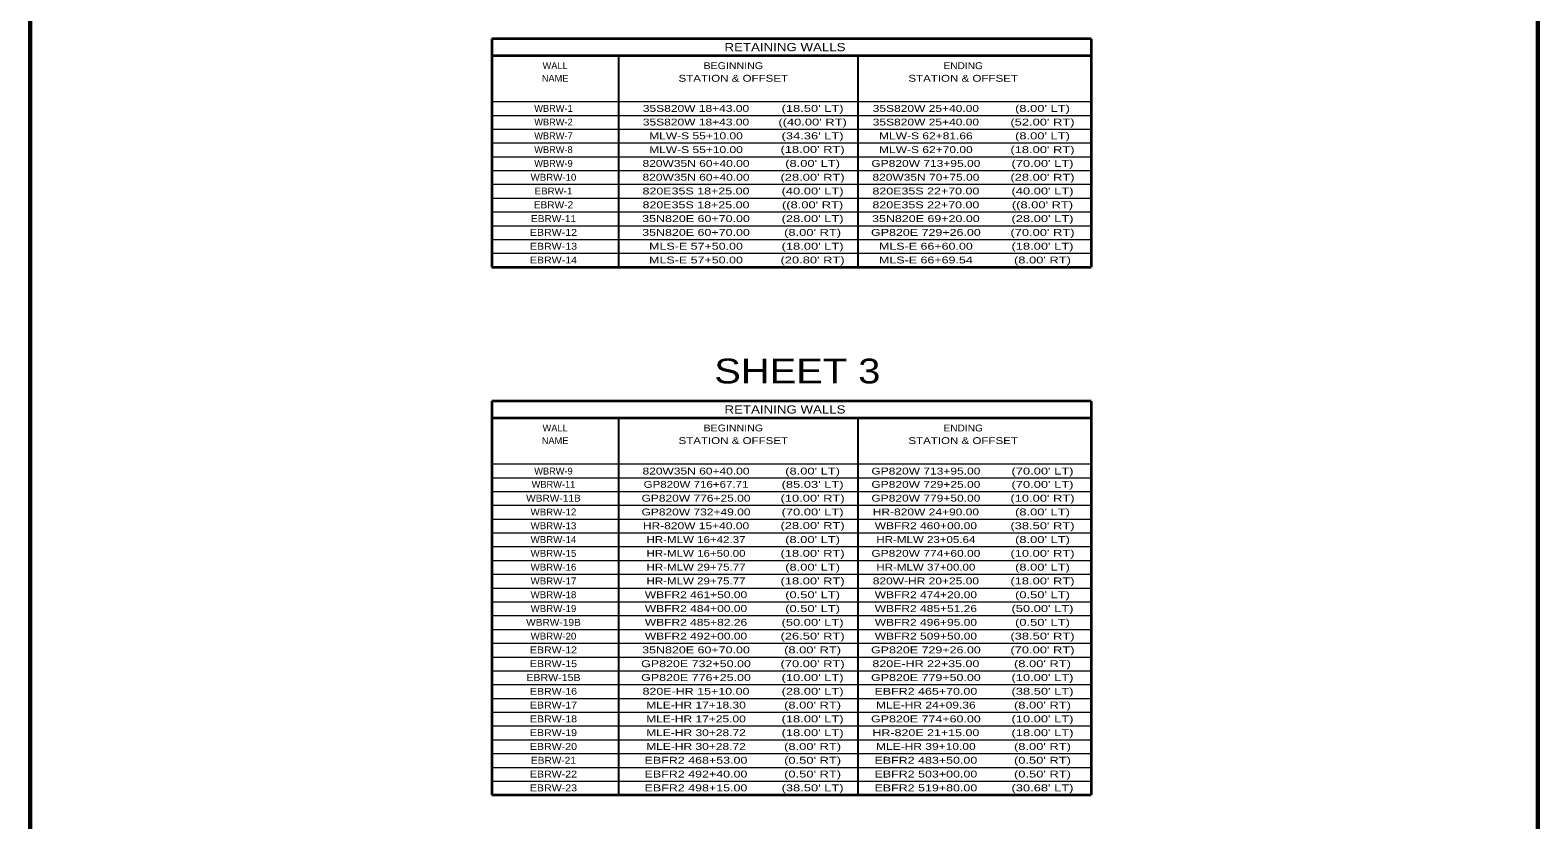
# Model space of a CAD drawing. Extents: x 2319482 to 2362028, y 6981189 to 6994467.
# Drawn here: x 2319482 to 2322105, y 6983285 to 6984659 of the extents above; entities that cross this region are included whole.
import ezdxf
from ezdxf.enums import TextEntityAlignment as Align

# ---------------------------------------------------------------- set-up
doc = ezdxf.new("R2010")
doc.units = 0
doc.header["$LTSCALE"] = 4.8
for name, color, linetype, lineweight in [('26', 7, 'Continuous', 13), ('45', 7, 'Continuous', 35), ('63', 7, 'Continuous', 60)]:
    doc.layers.add(name, color=color, linetype=linetype, lineweight=lineweight)

msp = doc.modelspace()

# ---------------------------------------------------------------- linework, layer by layer
at = {"layer": '26', "lineweight": 35}
for p, q in [((2321327.828, 6984643.503), (2320285.241, 6984643.503)), ((2320285.241, 6984643.503), (2320285.241, 6984246.37)), ((2321327.828, 6984643.503), (2321327.828, 6984246.37)), ((2320285.241, 6984614.703), (2321327.828, 6984614.703)), ((2320285.241, 6984246.37), (2321327.828, 6984246.37)), ((2321327.828, 6984013.126), (2320285.241, 6984013.126)), ((2320285.241, 6984013.126), (2320285.241, 6983327.993)), ((2321327.828, 6984013.126), (2321327.828, 6983327.993)), ((2320285.241, 6983984.326), (2321327.828, 6983984.326)), ((2320285.241, 6983327.993), (2321327.828, 6983327.993))]:
    msp.add_line(p, q, dxfattribs=at)
at = {"layer": '26', "lineweight": 25}
for p, q in [((2320505.241, 6984614.703), (2320505.241, 6984246.37)), ((2320921.935, 6984614.703), (2320921.935, 6984246.37)), ((2320505.241, 6983984.326), (2320505.241, 6983327.993)), ((2320921.935, 6983984.326), (2320921.935, 6983327.993))]:
    msp.add_line(p, q, dxfattribs=at)
at = {"layer": '26'}
for p, q in [((2320285.241, 6984534.37), (2321327.828, 6984534.37)), ((2320285.241, 6984510.37), (2321327.828, 6984510.37)), ((2320285.241, 6984486.37), (2321327.828, 6984486.37)), ((2320285.241, 6984462.37), (2321327.828, 6984462.37)), ((2320285.241, 6984438.37), (2321327.828, 6984438.37)), ((2320285.241, 6984414.37), (2321327.828, 6984414.37)), ((2320285.241, 6984390.37), (2321327.828, 6984390.37)), ((2320285.241, 6984366.37), (2321327.828, 6984366.37)), ((2320285.241, 6984342.37), (2321327.828, 6984342.37)), ((2320285.241, 6984318.37), (2321327.828, 6984318.37)), ((2320285.241, 6984294.37), (2321327.828, 6984294.37)), ((2320285.241, 6984270.37), (2321327.828, 6984270.37)), ((2320285.241, 6983903.993), (2321327.828, 6983903.993)), ((2320285.241, 6983879.993), (2321327.828, 6983879.993)), ((2320285.241, 6983855.993), (2321327.828, 6983855.993)), ((2320285.241, 6983831.993), (2321327.828, 6983831.993)), ((2320285.241, 6983807.993), (2321327.828, 6983807.993)), ((2320285.241, 6983783.993), (2321327.828, 6983783.993)), ((2320285.241, 6983759.993), (2321327.828, 6983759.993)), ((2320285.241, 6983735.993), (2321327.828, 6983735.993)), ((2320285.241, 6983711.993), (2321327.828, 6983711.993)), ((2320285.241, 6983687.993), (2321327.828, 6983687.993)), ((2320285.241, 6983663.993), (2321327.828, 6983663.993)), ((2320285.241, 6983639.993), (2321327.828, 6983639.993)), ((2320285.241, 6983615.993), (2321327.828, 6983615.993)), ((2320285.241, 6983591.993), (2321327.828, 6983591.993)), ((2320285.241, 6983567.993), (2321327.828, 6983567.993)), ((2320285.241, 6983543.993), (2321327.828, 6983543.993)), ((2320285.241, 6983519.993), (2321327.828, 6983519.993)), ((2320285.241, 6983495.993), (2321327.828, 6983495.993)), ((2320285.241, 6983471.993), (2321327.828, 6983471.993)), ((2320285.241, 6983447.993), (2321327.828, 6983447.993)), ((2320285.241, 6983423.993), (2321327.828, 6983423.993)), ((2320285.241, 6983399.993), (2321327.828, 6983399.993)), ((2320285.241, 6983375.993), (2321327.828, 6983375.993)), ((2320285.241, 6983351.993), (2321327.828, 6983351.993))]:
    msp.add_line(p, q, dxfattribs=at)
at = {"layer": '63'}
msp.add_lwpolyline([(2319481.784, 6985687.71), (2322105.179, 6985687.71), (2322105.179, 6981188.674), (2319481.784, 6981188.674)], close=True, dxfattribs=at)

# ---------------------------------------------------------------- texts
at = {"layer": '26'}
for s, height, width, p in [('RETAINING WALLS', 14.4, 1.2, (2320795.236, 6984621.904)), ('STATION & OFFSET', 12, 1.25, (2320705.236, 6984568.828)), ('BEGINNING', 12, 1.15, (2320705.237, 6984590.829)), ('STATION & OFFSET', 12, 1.25, (2321105.236, 6984568.829)), ('ENDING', 12, 1.1, (2321105.237, 6984590.827)), ('35S820W 18+43.00', 12, 1.3, (2320640.375, 6984516.425)), ("(18.50' LT)", 12, 1.4, (2320843.216, 6984516.424)), ('35S820W 25+40.00', 12, 1.3, (2321040.375, 6984516.425)), ("(8.00' LT)", 12, 1.4, (2321243.217, 6984516.424)), ('35S820W 18+43.00', 12, 1.3, (2320640.375, 6984492.724)), ("((40.00' RT)", 12, 1.4, (2320843.216, 6984492.723)), ('35S820W 25+40.00', 12, 1.3, (2321040.375, 6984492.724)), ("(52.00' RT)", 12, 1.4, (2321243.216, 6984492.723)), ('MLW-S 55+10.00', 12, 1.3, (2320640.374, 6984468.724)), ("(34.36' LT)", 12, 1.4, (2320843.216, 6984468.723)), ('MLW-S 62+81.66', 12, 1.3, (2321040.374, 6984468.724)), ("(8.00' LT)", 12, 1.4, (2321243.217, 6984468.723)), ('MLW-S 55+10.00', 12, 1.3, (2320640.374, 6984444.724)), ("(18.00' RT)", 12, 1.4, (2320843.216, 6984445.089)), ('MLW-S 62+70.00', 12, 1.3, (2321040.374, 6984444.724)), ("(18.00' RT)", 12, 1.4, (2321243.216, 6984444.723)), ('820W35N 60+40.00', 12, 1.3, (2320640.375, 6984420.724)), ("(8.00' LT)", 12, 1.4, (2320843.217, 6984420.723)), ('GP820W 713+95.00', 12, 1.3, (2321040.375, 6984420.724)), ("(70.00' LT)", 12, 1.4, (2321243.216, 6984420.723)), ('WBRW-10', 12, 1.05, (2320392.351, 6984396.724)), ('820W35N 60+40.00', 12, 1.3, (2320640.375, 6984396.724)), ("(28.00' RT)", 12, 1.4, (2320843.216, 6984396.723)), ('820W35N 70+75.00', 12, 1.3, (2321040.375, 6984396.724)), ("(28.00' RT)", 12, 1.4, (2321243.216, 6984396.723)), ('EBRW-1', 12, 1.05, (2320392.351, 6984372.724)), ('820E35S 18+25.00', 12, 1.35, (2320640.375, 6984372.724)), ("(40.00' LT)", 12, 1.4, (2320843.216, 6984372.723)), ('820E35S 22+70.00', 12, 1.35, (2321040.375, 6984372.724)), ("(40.00' LT)", 12, 1.4, (2321243.216, 6984372.723)), ('EBRW-2', 12, 1.1, (2320392.35, 6984348.724)), ('820E35S 18+25.00', 12, 1.35, (2320640.375, 6984348.724)), ("((8.00' RT)", 12, 1.4, (2320843.216, 6984348.723)), ('820E35S 22+70.00', 12, 1.35, (2321040.375, 6984348.724)), ("((8.00' RT)", 12, 1.4, (2321243.216, 6984348.723)), ('EBRW-11', 12, 1.1, (2320392.35, 6984324.724)), ('35N820E 60+70.00', 12, 1.35, (2320640.375, 6984324.724)), ("(28.00' LT)", 12, 1.4, (2320843.216, 6984324.723)), ('35N820E 69+20.00', 12, 1.35, (2321040.375, 6984324.724)), ("(28.00' LT)", 12, 1.4, (2321243.216, 6984324.723)), ('EBRW-12', 12, 1.15, (2320392.351, 6984300.724)), ('35N820E 60+70.00', 12, 1.35, (2320640.375, 6984300.724)), ("(8.00' RT)", 12, 1.4, (2320843.217, 6984300.723)), ('GP820E 729+26.00', 12, 1.35, (2321040.375, 6984300.724)), ("(70.00' RT)", 12, 1.4, (2321243.216, 6984300.723)), ('EBRW-13', 12, 1.15, (2320392.351, 6984276.724)), ('EBRW-14', 12, 1.15, (2320392.351, 6984252.724)), ('MLS-E 57+50.00', 12, 1.35, (2320640.374, 6984276.724)), ('MLS-E 57+50.00', 12, 1.35, (2320640.374, 6984252.724)), ("(20.80' RT)", 12, 1.4, (2320843.216, 6984252.723)), ("(18.00' LT)", 12, 1.4, (2320843.216, 6984276.723)), ('MLS-E 66+60.00', 12, 1.35, (2321040.374, 6984276.724)), ('MLS-E 66+69.54', 12, 1.35, (2321040.374, 6984252.724)), ("(18.00' LT)", 12, 1.4, (2321243.216, 6984276.723)), ("(8.00' RT)", 12, 1.4, (2321243.217, 6984252.723)), ('SHEET 3', 43.2, 1.2, (2320816.684, 6984043.936)), ('RETAINING WALLS', 14.4, 1.2, (2320795.236, 6983991.527)), ('STATION & OFFSET', 12, 1.25, (2320705.236, 6983938.451)), ('BEGINNING', 12, 1.15, (2320705.237, 6983960.452)), ('STATION & OFFSET', 12, 1.25, (2321105.236, 6983938.452)), ('ENDING', 12, 1.1, (2321105.237, 6983960.45)), ('820W35N 60+40.00', 12, 1.3, (2320640.375, 6983885.466)), ("(8.00' LT)", 12, 1.4, (2320843.217, 6983885.465)), ('GP820W 713+95.00', 12, 1.3, (2321040.375, 6983885.466)), ("(70.00' LT)", 12, 1.4, (2321243.216, 6983885.465)), ('GP820W 716+67.71', 12, 1.25, (2320640.374, 6983862.347)), ("(85.03' LT)", 12, 1.4, (2320843.216, 6983862.346)), ('GP820W 729+25.00', 12, 1.3, (2321040.375, 6983862.347)), ("(70.00' LT)", 12, 1.4, (2321243.216, 6983862.346)), ('WBRW-11B', 12, 1.1, (2320392.35, 6983838.347)), ('GP820W 776+25.00', 12, 1.3, (2320640.375, 6983838.347)), ("(10.00' RT)", 12, 1.4, (2320843.216, 6983838.346)), ('GP820W 779+50.00', 12, 1.3, (2321040.375, 6983838.347)), ("(10.00' RT)", 12, 1.4, (2321243.216, 6983838.346)), ('WBRW-12', 12, 1.05, (2320392.35, 6983814.348)), ('GP820W 732+49.00', 12, 1.3, (2320640.374, 6983814.348)), ("(70.00' LT)", 12, 1.4, (2320843.215, 6983814.347)), ('HR-820W 24+90.00', 12, 1.3, (2321040.374, 6983814.348)), ("(8.00' LT)", 12, 1.4, (2321243.216, 6983814.347)), ('WBRW-13', 12, 1.05, (2320392.35, 6983790.348)), ('HR-820W 15+40.00', 12, 1.3, (2320640.374, 6983790.348)), ("(28.00' RT)", 12, 1.4, (2320843.215, 6983790.713)), ('WBFR2 460+00.00', 12, 1.3, (2321040.373, 6983790.348)), ("(38.50' RT)", 12, 1.4, (2321243.215, 6983790.347)), ('WBRW-14', 12, 1.05, (2320392.35, 6983766.348)), ('HR-MLW 16+42.37', 12, 1.25, (2320640.373, 6983766.348)), ("(8.00' LT)", 12, 1.4, (2320843.216, 6983766.347)), ('HR-MLW 23+05.64', 12, 1.25, (2321040.373, 6983766.348)), ("(8.00' LT)", 12, 1.4, (2321243.216, 6983766.347)), ('WBRW-15', 12, 1.05, (2320392.35, 6983742.348)), ('HR-MLW 16+50.00', 12, 1.25, (2320640.373, 6983742.348)), ("(18.00' RT)", 12, 1.4, (2320843.215, 6983742.347)), ('WBRW-16', 12, 1.05, (2320392.349, 6983718.348)), ('HR-MLW 29+75.77', 12, 1.25, (2320640.373, 6983718.348)), ("(8.00' LT)", 12, 1.4, (2320843.216, 6983718.347)), ('HR-MLW 37+00.00', 12, 1.25, (2321040.373, 6983718.348)), ("(8.00' LT)", 12, 1.4, (2321243.216, 6983718.347)), ('WBRW-17', 12, 1.05, (2320392.35, 6983694.348)), ('HR-MLW 29+75.77', 12, 1.25, (2320640.373, 6983694.348)), ("(18.00' RT)", 12, 1.4, (2320843.215, 6983694.347)), ('WBRW-18', 12, 1.05, (2320392.35, 6983670.348)), ('WBFR2 461+50.00', 12, 1.3, (2320640.373, 6983670.348)), ("(0.50' LT)", 12, 1.4, (2320843.216, 6983670.347)), ('WBFR2 474+20.00', 12, 1.3, (2321040.373, 6983670.348)), ("(0.50' LT)", 12, 1.4, (2321243.216, 6983670.347)), ('WBRW-19', 12, 1.05, (2320392.349, 6983646.348)), ('WBFR2 484+00.00', 12, 1.3, (2320640.373, 6983646.348)), ("(50.00' LT)", 12, 1.4, (2320843.215, 6983622.347)), ("(0.50' LT)", 12, 1.4, (2320843.216, 6983646.347)), ('WBFR2 485+51.26', 12, 1.3, (2321040.373, 6983646.348)), ("(50.00' LT)", 12, 1.4, (2321243.215, 6983646.347)), ("(0.50' LT)", 12, 1.4, (2321243.216, 6983622.347)), ('WBRW-19B', 12, 1.1, (2320392.349, 6983622.348)), ('WBRW-20', 12, 1.05, (2320392.35, 6983598.348)), ('WBFR2 485+82.26', 12, 1.3, (2320640.373, 6983622.348)), ('WBFR2 492+00.00', 12, 1.3, (2320640.373, 6983598.348)), ("(26.50' RT)", 12, 1.4, (2320843.215, 6983598.347)), ('WBFR2 496+95.00', 12, 1.3, (2321040.373, 6983622.348)), ('WBFR2 509+50.00', 12, 1.3, (2321040.373, 6983598.348)), ("(38.50' RT)", 12, 1.4, (2321243.215, 6983598.347)), ('EBRW-12', 12, 1.15, (2320392.35, 6983574.348)), ('35N820E 60+70.00', 12, 1.35, (2320640.374, 6983574.348)), ("(8.00' RT)", 12, 1.4, (2320843.216, 6983574.347)), ('GP820E 729+26.00', 12, 1.35, (2321040.374, 6983574.348)), ("(70.00' RT)", 12, 1.4, (2321243.215, 6983574.347)), ('EBRW-15', 12, 1.15, (2320392.35, 6983550.348)), ('GP820E 732+50.00', 12, 1.35, (2320640.374, 6983550.348)), ("(70.00' RT)", 12, 1.4, (2320843.215, 6983550.347)), ('820E-HR 22+35.00', 12, 1.35, (2321040.374, 6983550.348)), ("(8.00' RT)", 12, 1.4, (2321243.216, 6983550.347)), ('EBRW-15B', 12, 1.15, (2320392.349, 6983526.348)), ('GP820E 776+25.00', 12, 1.35, (2320640.374, 6983526.348)), ("(10.00' LT)", 12, 1.4, (2320843.215, 6983526.347)), ('GP820E 779+50.00', 12, 1.35, (2321040.374, 6983526.348)), ("(10.00' LT)", 12, 1.4, (2321243.215, 6983526.347)), ('EBRW-16', 12, 1.15, (2320392.349, 6983502.349)), ('820E-HR 15+10.00', 12, 1.35, (2320640.374, 6983502.349)), ("(28.00' LT)", 12, 1.4, (2320843.215, 6983502.348)), ('EBFR2 465+70.00', 12, 1.35, (2321040.373, 6983502.349)), ("(38.50' LT)", 12, 1.4, (2321243.215, 6983502.348)), ('EBRW-17', 12, 1.15, (2320392.35, 6983478.349)), ('MLE-HR 17+18.30', 12, 1.3, (2320640.373, 6983478.349)), ("(8.00' RT)", 12, 1.4, (2320843.216, 6983478.348)), ('MLE-HR 24+09.36', 12, 1.3, (2321040.373, 6983478.349)), ("(8.00' RT)", 12, 1.4, (2321243.216, 6983478.348)), ('EBRW-18', 12, 1.15, (2320392.35, 6983454.349)), ('MLE-HR 17+25.00', 12, 1.3, (2320640.373, 6983454.349)), ("(18.00' LT)", 12, 1.4, (2320843.215, 6983454.348)), ('EBRW-19', 12, 1.15, (2320392.349, 6983430.349)), ('MLE-HR 30+28.72', 12, 1.3, (2320640.373, 6983430.349)), ("(18.00' LT)", 12, 1.4, (2320843.215, 6983430.348)), ('HR-820E 21+15.00', 12, 1.35, (2321040.374, 6983430.349)), ("(18.00' LT)", 12, 1.4, (2321243.215, 6983430.348)), ('EBRW-20', 12, 1.15, (2320392.35, 6983406.349)), ('MLE-HR 30+28.72', 12, 1.3, (2320640.373, 6983406.349)), ("(8.00' RT)", 12, 1.4, (2320843.216, 6983406.348)), ('MLE-HR 39+10.00', 12, 1.3, (2321040.373, 6983406.349)), ("(8.00' RT)", 12, 1.4, (2321243.216, 6983406.348)), ('EBRW-21', 12, 1.1, (2320392.349, 6983382.349)), ('EBFR2 468+53.00', 12, 1.35, (2320640.373, 6983382.349)), ("(0.50' RT)", 12, 1.4, (2320843.216, 6983382.348)), ('EBFR2 483+50.00', 12, 1.35, (2321040.373, 6983382.349)), ("(0.50' RT)", 12, 1.4, (2321243.216, 6983382.348)), ('EBRW-22', 12, 1.15, (2320392.35, 6983358.349)), ('EBRW-23', 12, 1.15, (2320392.35, 6983334.349)), ('EBFR2 492+40.00', 12, 1.35, (2320640.373, 6983358.349)), ('EBFR2 498+15.00', 12, 1.35, (2320640.373, 6983334.349)), ("(38.50' LT)", 12, 1.4, (2320843.215, 6983334.348)), ("(0.50' RT)", 12, 1.4, (2320843.216, 6983358.348)), ('EBFR2 503+00.00', 12, 1.35, (2321040.373, 6983358.349)), ('EBFR2 519+80.00', 12, 1.35, (2321040.373, 6983334.349)), ("(30.68' LT)", 12, 1.4, (2321243.215, 6983334.348)), ("(0.50' RT)", 12, 1.4, (2321243.216, 6983358.348))]:
    msp.add_text(s, height=height, dxfattribs=dict(at, width=width)).set_placement(p, align=Align.CENTER)
for s, p in [('NAME', (2320395.235, 6984568.828)), ('WALL', (2320395.236, 6984590.828)), ('WBRW-1', (2320392.351, 6984516.425)), ('WBRW-2', (2320392.35, 6984492.724)), ('WBRW-7', (2320392.35, 6984468.724)), ('WBRW-8', (2320392.35, 6984444.724)), ('WBRW-9', (2320392.35, 6984420.724)), ('NAME', (2320395.235, 6983938.451)), ('WALL', (2320395.236, 6983960.451)), ('WBRW-9', (2320392.35, 6983885.466)), ('WBRW-11', (2320392.35, 6983862.347))]:
    msp.add_text(s, height=12, dxfattribs=at).set_placement(p, align=Align.CENTER)
at = {"layer": '45'}
for s, width, p in [('GP820W 774+60.00', 1.3, (2321040.374, 6983742.348)), ("(10.00' RT)", 1.4, (2321243.215, 6983742.347)), ('820W-HR 20+25.00', 1.3, (2321040.374, 6983694.348)), ("(18.00' RT)", 1.4, (2321243.215, 6983694.347)), ('GP820E 774+60.00', 1.35, (2321040.374, 6983454.349)), ("(10.00' LT)", 1.4, (2321243.215, 6983454.348))]:
    msp.add_text(s, height=12, dxfattribs=dict(at, width=width)).set_placement(p, align=Align.CENTER)

doc.saveas('drawing.dxf')
